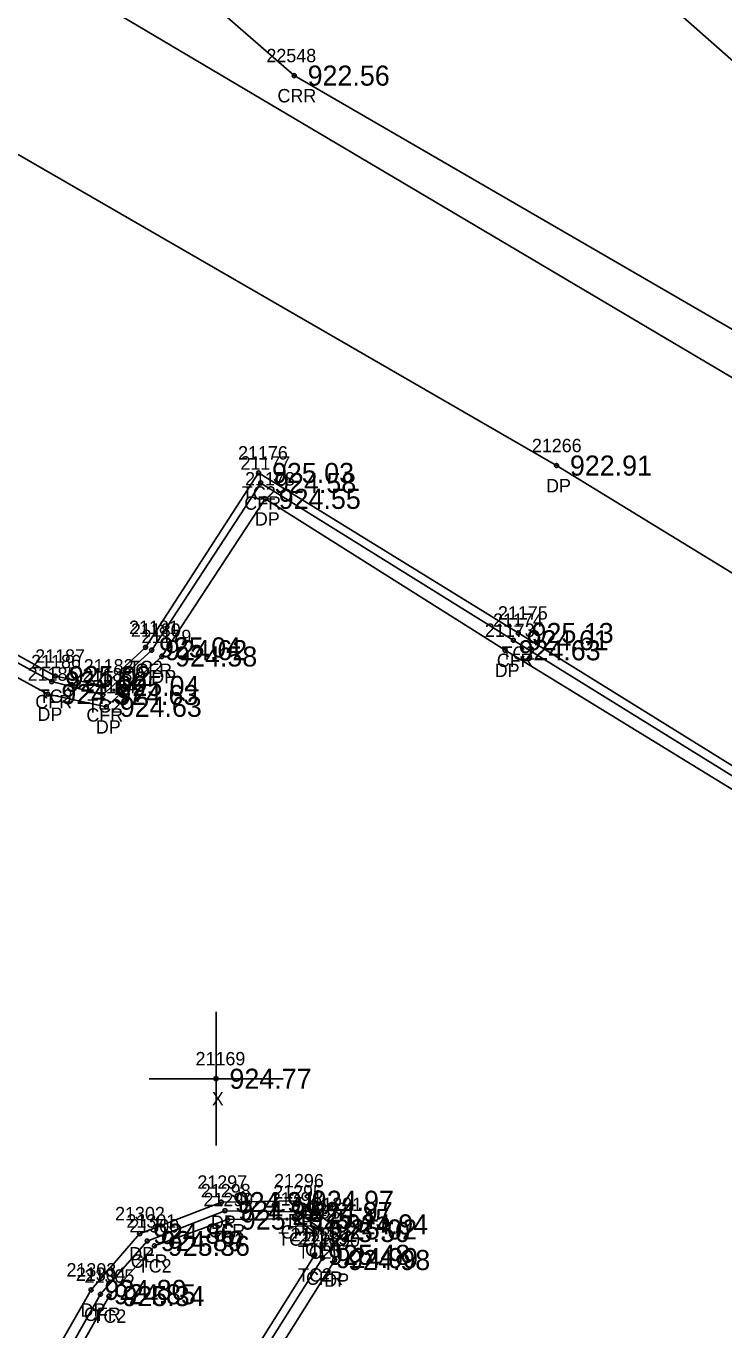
# Model space of a CAD drawing. Extents: x 1576181 to 1577685, y 1099396 to 1101490.
# Drawn here: x 1576907.5 to 1576959.6, y 1100279.9 to 1100377.3 of the extents above; entities that cross this region are included whole.
import ezdxf

# ---------------------------------------------------------------- set-up
doc = ezdxf.new("R2010")
doc.units = 0
for name, color, linetype in [('RD_DTM_BkLn2', 7, 'Continuous'), ('RD_EX_Conc', 7, 'Continuous'), ('RD_EX_Conc_txCode', 7, 'Continuous'), ('RD_EX_Driveway', 7, 'Continuous'), ('RD_EX_Driveway_txCode', 7, 'Continuous'), ('RD_EX_H2O', 7, 'Continuous'), ('RD_EX_H2O_txCode', 7, 'Continuous'), ('RD_EX_Misc', 7, 'Continuous'), ('RD_EX_Misc_txCode', 7, 'Continuous'), ('RD_EX_TX_Conc_ELEV', 7, 'Continuous'), ('RD_EX_TX_Driveway_ELEV', 7, 'Continuous'), ('RD_EX_TX_H2O_ELEV', 7, 'Continuous'), ('RD_EX_TX_Misc_ELEV', 7, 'Continuous'), ('RD_SMD_Locator', 7, 'Continuous')]:
    doc.layers.add(name, color=color, linetype=linetype)

msp = doc.modelspace()

# ---------------------------------------------------------------- linework, layer by layer
at = {"layer": 'RD_DTM_BkLn2'}
for points in [[(1576910.964, 1100407.001), (1576940.332, 1100392.339), (1576974.418, 1100362.262), (1577019.121, 1100334.748), (1577060.028, 1100308.773), (1577094.531, 1100282.76), (1577137.683, 1100262.427), (1577168.476, 1100246.276), (1577215.797, 1100216.273), (1577257.089, 1100185.269), (1577298.116, 1100162.185), (1577331.938, 1100143.387)], [(1576981.641, 1100308.772), (1576944.221, 1100331.974), (1576924.823, 1100343.94), (1576916.376, 1100330.898), (1576913.272, 1100328.019), (1576909.644, 1100328.751), (1576892.858, 1100338.06), (1576870.533, 1100297.878), (1576883.045, 1100290.892), (1576884.239, 1100289.373), (1576883.702, 1100287.814), (1576876.741, 1100285.714), (1576869.346, 1100287.53), (1576863.783, 1100292.601), (1576859.799, 1100299.85), (1576858.159, 1100305.393)], [(1576950.428, 1100253.929), (1576920.799, 1100272.396), (1576929.017, 1100285.487), (1576929.003, 1100287.192), (1576927.528, 1100288.17), (1576922.503, 1100288.122), (1576917.041, 1100286.162), (1576913.654, 1100282.404), (1576887.247, 1100235.73)]]:
    msp.add_lwpolyline(points, dxfattribs=at)
at = {"layer": 'RD_EX_Conc'}
for points in [[(1576981.4, 1100308.175), (1576943.854, 1100331.434), (1576924.982, 1100343.186), (1576916.835, 1100330.69), (1576913.186, 1100327.347), (1576909.365, 1100328.339), (1576893.139, 1100337.219), (1576871.484, 1100298.091), (1576883.401, 1100291.404), (1576884.862, 1100289.303), (1576883.985, 1100287.299), (1576876.72, 1100284.984), (1576869.052, 1100286.957), (1576863.263, 1100292.262), (1576859.183, 1100299.543), (1576857.641, 1100305.136)], [(1576950.686, 1100254.487), (1576921.564, 1100272.475), (1576929.602, 1100285.245), (1576929.528, 1100287.387), (1576927.709, 1100288.698), (1576922.308, 1100288.785), (1576916.503, 1100286.517), (1576913.006, 1100282.543), (1576886.711, 1100236.108)]]:
    msp.add_lwpolyline(points, dxfattribs=at)
at = {"layer": 'RD_EX_Driveway'}
for points in [[(1576906.579, 1100382.841), (1576964.438, 1100348.558), (1576998.206, 1100327.412)], [(1576899.64, 1100371.947), (1576900.229, 1100371.557), (1576947.086, 1100344.489), (1576990.818, 1100317.698)], [(1576980.993, 1100307.534), (1576943.247, 1100330.682), (1576925.325, 1100342), (1576917.589, 1100330.217), (1576913.446, 1100326.455), (1576909.081, 1100327.403), (1576893.369, 1100335.997), (1576872.46, 1100298.43), (1576883.975, 1100292.106), (1576885.751, 1100289.247), (1576884.594, 1100286.58), (1576876.771, 1100284.193), (1576868.68, 1100286.222), (1576862.578, 1100291.757), (1576858.385, 1100299.115), (1576856.774, 1100304.988), (1576856.691, 1100315.855), (1576858.248, 1100324.631)], [(1576951.058, 1100255.291), (1576922.81, 1100272.792), (1576930.511, 1100285.101), (1576930.352, 1100287.763), (1576927.798, 1100289.531), (1576922.044, 1100289.43), (1576915.936, 1100287.07), (1576912.303, 1100282.866), (1576885.713, 1100236.458)]]:
    msp.add_lwpolyline(points, dxfattribs=at)
at = {"layer": 'RD_EX_H2O'}
msp.add_lwpolyline([(1576900.366, 1100401.58), (1576904.277, 1100393.845), (1576927.487, 1100373.64), (1576968.41, 1100349.917), (1577010.575, 1100322.364), (1577050.409, 1100297.369), (1577087.053, 1100275.192), (1577127.196, 1100251.289), (1577165.433, 1100227.76), (1577206.901, 1100201.892), (1577246.285, 1100176.806), (1577287.622, 1100151.195), (1577327.033, 1100134.924)], dxfattribs=at)
at = {"layer": 'RD_EX_Misc'}
for p, q in [((1576921.648, 1100293.652), (1576921.648, 1100303.652)), ((1576916.648, 1100298.652), (1576926.648, 1100298.652))]:
    msp.add_line(p, q, dxfattribs=at)
at = {"layer": 'RD_SMD_Locator'}
for centre in [(1576927.487, 1100373.64), (1576947.086, 1100344.489), (1576924.823, 1100343.94), (1576924.982, 1100343.186), (1576925.325, 1100342), (1576944.221, 1100331.974), (1576916.376, 1100330.898), (1576916.835, 1100330.69), (1576943.247, 1100330.682), (1576943.854, 1100331.434), (1576917.589, 1100330.217), (1576909.644, 1100328.751), (1576909.365, 1100328.339), (1576913.272, 1100328.019), (1576909.081, 1100327.403), (1576913.186, 1100327.347), (1576913.446, 1100326.455), (1576921.648, 1100298.652), (1576922.044, 1100289.43), (1576922.308, 1100288.785), (1576927.798, 1100289.531), (1576922.503, 1100288.122), (1576927.528, 1100288.17), (1576927.709, 1100288.698), (1576915.936, 1100287.07), (1576929.003, 1100287.192), (1576929.528, 1100287.387), (1576930.352, 1100287.763), (1576916.503, 1100286.517), (1576917.041, 1100286.162), (1576929.017, 1100285.487), (1576929.602, 1100285.245), (1576930.511, 1100285.101), (1576912.303, 1100282.866), (1576913.006, 1100282.543), (1576913.654, 1100282.404)]:
    msp.add_circle(centre, 0.15, dxfattribs=at)

# ---------------------------------------------------------------- texts
at = {"layer": 'RD_EX_Conc_txCode'}
for s, p in [('21176', (1576923.288, 1100344.94)), ('21177', (1576923.47, 1100344.186)), ('TC2', (1576923.579, 1100341.94)), ('CFR', (1576923.754, 1100341.186)), ('21175', (1576942.709, 1100332.974)), ('21181', (1576915.147, 1100331.898)), ('21174', (1576942.342, 1100332.434)), ('21180', (1576915.284, 1100331.69)), ('TC2', (1576942.977, 1100329.974)), ('21186', (1576907.83, 1100329.339)), ('21187', (1576908.133, 1100329.751)), ('21182', (1576911.76, 1100329.019)), ('TC2', (1576915.132, 1100328.898)), ('CFR', (1576942.626, 1100329.434)), ('21183', (1576911.674, 1100328.347)), ('CFR', (1576915.607, 1100328.69)), ('CFR', (1576908.137, 1100326.339)), ('TC2', (1576908.4, 1100326.751)), ('TC2', (1576912.028, 1100326.019)), ('CFR', (1576911.958, 1100325.347)), ('21298', (1576920.513, 1100289.785)), ('21299', (1576920.708, 1100289.122)), ('21294', (1576925.733, 1100289.17)), ('21295', (1576925.914, 1100289.698)), ('21293', (1576927.208, 1100288.192)), ('21292', (1576927.733, 1100288.387)), ('21301', (1576914.952, 1100287.517)), ('21300', (1576915.167, 1100287.162)), ('CFR', (1576921.08, 1100286.785)), ('TC2', (1576921.259, 1100286.122)), ('TC2', (1576926.284, 1100286.17)), ('CFR', (1576926.48, 1100286.698)), ('21288', (1576927.222, 1100286.487)), ('21289', (1576927.807, 1100286.245)), ('TC2', (1576927.759, 1100285.192)), ('CFR', (1576928.3, 1100285.387)), ('CFR', (1576915.275, 1100284.517)), ('TC2', (1576915.797, 1100284.162)), ('21304', (1576911.172, 1100283.543)), ('21305', (1576911.82, 1100283.404)), ('TC2', (1576927.773, 1100283.487)), ('CFR', (1576928.374, 1100283.245)), ('CFR', (1576911.778, 1100280.543)), ('TC2', (1576912.41, 1100280.404))]:
    msp.add_text(s, height=1, dxfattribs=at).set_placement(p)
at = {"layer": 'RD_EX_Driveway_txCode'}
for s, p in [('21266', (1576945.243, 1100345.489)), ('21178', (1576923.814, 1100343)), ('DP', (1576946.306, 1100342.489)), ('DP', (1576924.546, 1100340)), ('21179', (1576916.077, 1100331.217)), ('21173', (1576941.735, 1100331.682)), ('21185', (1576907.569, 1100328.403)), ('DP', (1576916.809, 1100328.217)), ('DP', (1576942.467, 1100328.682)), ('21184', (1576911.934, 1100327.455)), ('DP', (1576908.302, 1100325.403)), ('DP', (1576912.666, 1100324.455)), ('21297', (1576920.249, 1100290.43)), ('21296', (1576925.98, 1100290.531)), ('21302', (1576914.102, 1100288.07)), ('21291', (1576928.84, 1100288.763)), ('DP', (1576921.264, 1100287.43)), ('DP', (1576927.019, 1100287.531)), ('21290', (1576928.676, 1100286.101)), ('DP', (1576915.157, 1100285.07)), ('DP', (1576929.572, 1100285.763)), ('21303', (1576910.468, 1100283.866)), ('DP', (1576929.731, 1100283.101)), ('DP', (1576911.523, 1100280.866))]:
    msp.add_text(s, height=1, dxfattribs=at).set_placement(p)
at = {"layer": 'RD_EX_H2O_txCode'}
for s, p in [('22548', (1576925.408, 1100374.64)), ('CRR', (1576926.235, 1100371.64))]:
    msp.add_text(s, height=1, dxfattribs=at).set_placement(p)
at = {"layer": 'RD_EX_Misc_txCode'}
for s, p in [('21169', (1576920.113, 1100299.652)), ('X', (1576921.333, 1100296.652))]:
    msp.add_text(s, height=1, dxfattribs=at).set_placement(p)
at = {"layer": 'RD_EX_TX_Conc_ELEV'}
for s, p in [('925.03', (1576925.823, 1100343.19)), ('924.58', (1576925.982, 1100342.436)), ('924.61', (1576944.854, 1100330.684)), ('925.13', (1576945.221, 1100331.224)), ('925.04', (1576917.376, 1100330.148)), ('924.62', (1576917.835, 1100329.94)), ('924.56', (1576910.365, 1100327.589)), ('925.02', (1576910.644, 1100328.001)), ('924.63', (1576914.186, 1100326.597)), ('925.04', (1576914.272, 1100327.269)), ('924.99', (1576923.308, 1100288.035)), ('925.45', (1576928.528, 1100287.42)), ('924.97', (1576928.709, 1100287.948)), ('925.46', (1576923.503, 1100287.372)), ('925.50', (1576930.003, 1100286.442)), ('925.02', (1576930.528, 1100286.637)), ('924.89', (1576917.503, 1100285.767)), ('925.36', (1576918.041, 1100285.412)), ('925.48', (1576930.017, 1100284.737)), ('924.99', (1576930.602, 1100284.495)), ('924.85', (1576914.006, 1100281.793)), ('925.34', (1576914.654, 1100281.654))]:
    msp.add_text(s, height=1.5, dxfattribs=at).set_placement(p)
at = {"layer": 'RD_EX_TX_Driveway_ELEV'}
for s, p in [('922.91', (1576948.086, 1100343.739)), ('924.55', (1576926.325, 1100341.25)), ('924.58', (1576918.589, 1100329.467)), ('924.63', (1576944.247, 1100329.932)), ('924.57', (1576910.081, 1100326.653)), ('924.63', (1576914.446, 1100325.705)), ('924.91', (1576923.044, 1100288.68)), ('924.97', (1576928.798, 1100288.781)), ('924.94', (1576931.352, 1100287.013)), ('924.86', (1576916.936, 1100286.32)), ('924.98', (1576931.511, 1100284.351)), ('924.80', (1576913.303, 1100282.116))]:
    msp.add_text(s, height=1.5, dxfattribs=at).set_placement(p)
at = {"layer": 'RD_EX_TX_H2O_ELEV'}
msp.add_text('922.56', height=1.5, dxfattribs=at).set_placement((1576928.487, 1100372.89))
at = {"layer": 'RD_EX_TX_Misc_ELEV'}
msp.add_text('924.77', height=1.5, dxfattribs=at).set_placement((1576922.648, 1100297.902))

doc.saveas('drawing.dxf')
